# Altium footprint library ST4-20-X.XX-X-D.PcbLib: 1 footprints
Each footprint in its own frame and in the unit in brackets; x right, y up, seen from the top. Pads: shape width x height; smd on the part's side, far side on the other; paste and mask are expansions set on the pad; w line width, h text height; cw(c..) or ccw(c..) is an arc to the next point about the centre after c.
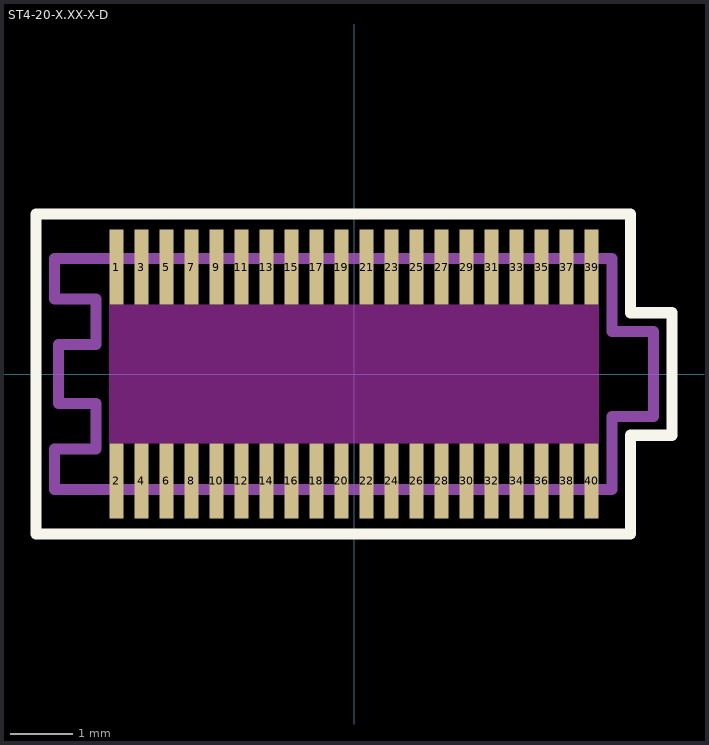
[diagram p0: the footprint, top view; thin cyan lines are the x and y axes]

## ST4-20-X.XX-X-D [mm]
pads (40):
  rect 0.23x1.2 smd paste-0.015 mask+0.05: 1(-3.8,1.71) 2(-3.8,-1.71) 3(-3.4,1.71) 4(-3.4,-1.71) 5(-3,1.71) 6(-3,-1.71) 7(-2.6,1.71) 8(-2.6,-1.71) 9(-2.2,1.71) 10(-2.2,-1.71) 11(-1.8,1.71) 12(-1.8,-1.71) 13(-1.4,1.71) 14(-1.4,-1.71) 15(-1,1.71) 16(-1,-1.71) 17(-0.6,1.71) 18(-0.6,-1.71) 19(-0.2,1.71) 20(-0.2,-1.71) 21(0.2,1.71) 22(0.2,-1.71) 23(0.6,1.71) 24(0.6,-1.71) 25(1,1.71) 26(1,-1.71) 27(1.4,1.71) 28(1.4,-1.71) 29(1.8,1.71) 30(1.8,-1.71) 31(2.2,1.71) 32(2.2,-1.71) 33(2.6,1.71) 34(2.6,-1.71) 35(3,1.71) 36(3,-1.71) 37(3.4,1.71) 38(3.4,-1.71) 39(3.8,1.71) 40(3.8,-1.71)
Top Overlay:
  lines w0.178: -5.09,-2.56 -5.09,2.56 4.425,2.56 4.425,0.98 5.09,0.98 5.09,-0.98 4.425,-0.98 4.425,-2.56 -5.09,-2.56
Keep-Out Layer:
  region: -3.915,1.11 3.915,1.11 3.915,-1.11 -3.915,-1.11
Mechanical 1:
  lines w0.178: -4.79,-1.85 -4.79,-1.2 -4.125,-1.2 -4.125,-0.47 -4.725,-0.47 -4.725,0.47 -4.125,0.47 -4.125,1.2 -4.79,1.2 -4.79,1.85 4.125,1.85 4.125,0.68 4.79,0.68 4.79,-0.68 4.125,-0.68 4.125,-1.85 -4.79,-1.85
  text "J1" at -0.446,-0.457 h0.76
